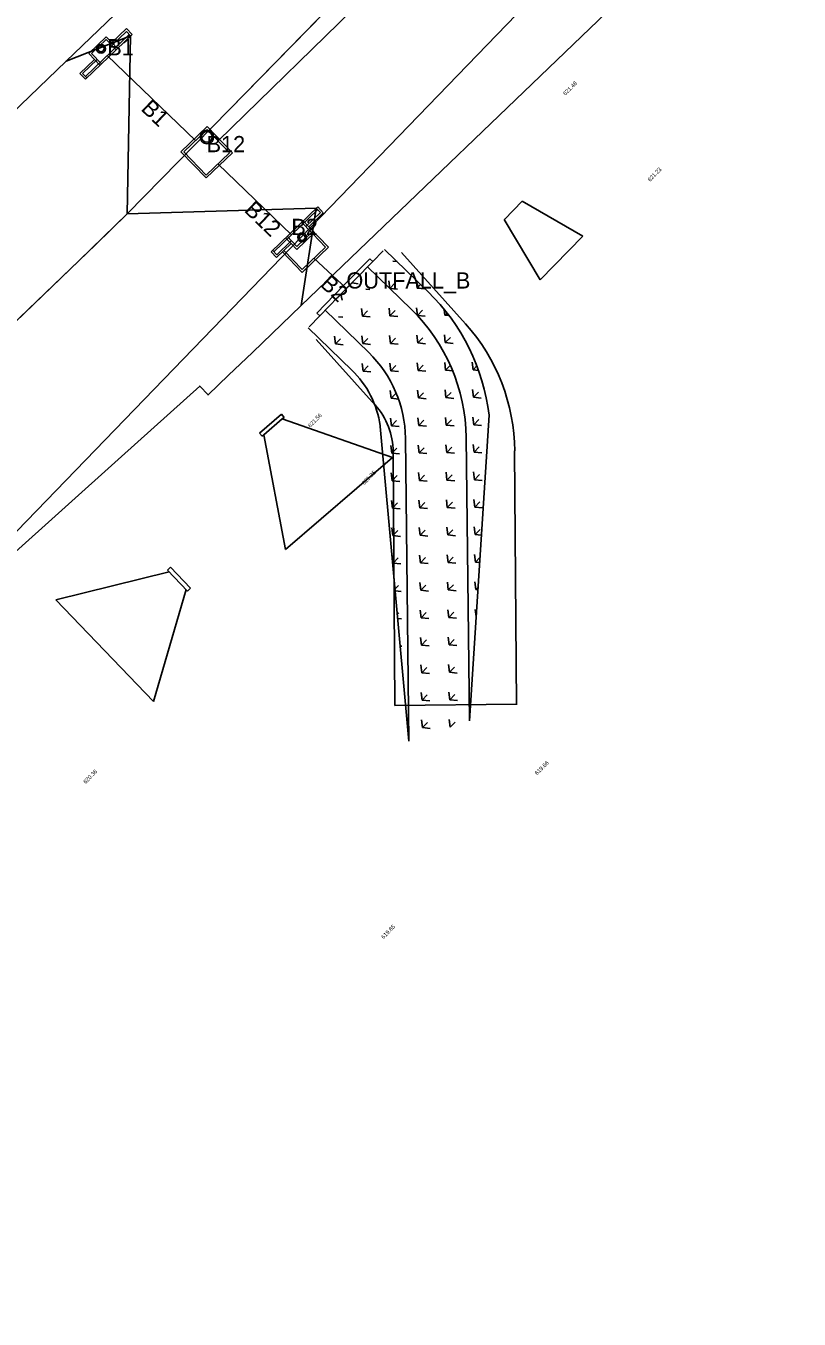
# Model space of a CAD drawing. Extents: x 2253035 to 2279930, y 13774972 to 13793443.
# Drawn here: x 2255239.2 to 2255430.2, y 13790865.4 to 13791184.9 of the extents above; entities that cross this region are included whole.
import ezdxf

# ---------------------------------------------------------------- set-up
doc = ezdxf.new("R2010")
doc.units = 0
for name, color, linetype in [('E_Utility_ATT_Fiber', 7, 'Continuous'), ('E_Utility_ATT_Xbox', 7, 'Continuous'), ('E_Utility_Electric_Overhead Electric Power Line_OE_Description', 7, 'Continuous'), ('E_Utility_Electric_Overhead Electric Power Line_OE_Elevation', 7, 'Continuous'), ('E_Utility_Electric_Service Pole Electric_SPLE_point', 7, 'Continuous'), ('E_Utility_Fiber Optic_Fiber Optic Cable_FOC', 7, 'Continuous'), ('E_Utility_Gas_Gas Line_GL_Description', 7, 'Continuous'), ('E_Utility_Gas_Gas Line_GL_Elevation', 7, 'Continuous'), ('E_Utility_Telephone_Manhole Telephone_MHT_Description', 7, 'Continuous'), ('E_Utility_Water_Water Line_WL_Elevation', 7, 'Continuous'), ('E_Utility_Water_Water Valve_WV_Elevation', 7, 'Continuous')]:
    doc.layers.add(name, color=color, linetype=linetype)

msp = doc.modelspace()

# ---------------------------------------------------------------- linework, layer by layer
at = {"layer": 'E_Utility_ATT_Fiber'}
for p, q in [((2255331.7, 13791207.4), (2255289.47, 13791164.26)), ((2255307.2, 13791115.81), (2255399.18, 13791204.14)), ((2255265.06, 13791182.43), (2255249.13, 13791176.15)), ((2255249.13, 13791176.15), (2255265.06, 13791182.43)), ((2255264.21, 13791138.47), (2255265.06, 13791182.43)), ((2255265.06, 13791182.43), (2255264.21, 13791138.47)), ((2255264.21, 13791138.47), (2255289.47, 13791164.26)), ((2255289.47, 13791164.26), (2255264.21, 13791138.47)), ((2255256.38, 13791130.82), (2255264.21, 13791138.47)), ((2255264.21, 13791138.47), (2255310.9, 13791139.84)), ((2255310.9, 13791139.84), (2255307.2, 13791115.81)), ((2255252.37, 13791126.93), (2255256.38, 13791130.82)), ((2255062.92, 13790944.99), (2255252.37, 13791126.93))]:
    msp.add_line(p, q, dxfattribs=at)
for points in [[(2255375.55, 13791298.97), (2255354.02, 13791277.09), (2255341.17, 13791264.54), (2255249.13, 13791176.15)], [(2255289.47, 13791164.26), (2255369.58, 13791246.26), (2255386.15, 13791263.21)], [(2255249.13, 13791176.15), (2255226.58, 13791154.5), (2255225.88, 13791155.18)]]:
    msp.add_lwpolyline(points, dxfattribs=at)
msp.add_lwpolyline([(2255310.9, 13791139.84), (2255307.22, 13791115.83), (2255295.13, 13791104.21), (2255289.23, 13791098.55), (2255284.2, 13791093.71), (2255282.12, 13791095.87), (2255262.79, 13791078.49), (2255121.12, 13790951.06), (2255099.87, 13790931.94), (2255092.37, 13790924.75), (2255033.91, 13790865.37), (2255030.7, 13790879.5), (2255003.84, 13790885.26), (2255037.34, 13790919.6), (2255062.92, 13790944.99), (2255252.37, 13791126.93), (2255264.21, 13791138.47)], close=True, dxfattribs=at)
at = {"layer": 'E_Utility_ATT_Xbox'}
for p, q in [((2255257.22, 13791179.76), (2255257.22, 13791179.76)), ((2255258.26, 13791178.68), (2255258.26, 13791178.68)), ((2255260.06, 13791180.41), (2255260.06, 13791180.41)), ((2255256.46, 13791176.95), (2255256.46, 13791176.95)), ((2255259.3, 13791177.6), (2255259.3, 13791177.6)), ((2255281.06, 13791156.55), (2255281.06, 13791156.55)), ((2255286.71, 13791156.44), (2255286.71, 13791156.44)), ((2255283.83, 13791153.67), (2255283.83, 13791153.67)), ((2255280.94, 13791150.9), (2255280.94, 13791150.9)), ((2255286.6, 13791150.78), (2255286.6, 13791150.78)), ((2255304.77, 13791133.23), (2255304.77, 13791133.23)), ((2255310.43, 13791133.11), (2255310.43, 13791133.11)), ((2255304.66, 13791127.57), (2255304.66, 13791127.57)), ((2255307.54, 13791130.34), (2255307.54, 13791130.34)), ((2255310.31, 13791127.46), (2255310.31, 13791127.46)), ((2255316.98, 13791118.56), (2255319.77, 13791121.43)), ((2255319.77, 13791121.43), (2255321.23, 13791121.14)), ((2255316.98, 13791118.56), (2255317.3, 13791117.11)), ((2255318.37, 13791119.99), (2255318.37, 13791119.99)), ((2255318.37, 13791119.99), (2255318.37, 13791119.99))]:
    msp.add_line(p, q, dxfattribs=at)
at = {"layer": 'E_Utility_Electric_Overhead Electric Power Line_OE_Description'}
for p, q in [((2255327.45, 13791129.32), (2255324.85, 13791126.65)), ((2255327.79, 13791129.66), (2255338.55, 13791119.19)), ((2255323.61, 13791125.37), (2255334.36, 13791114.89)), ((2255329.84, 13791126.73), (2255330.88, 13791126.63)), ((2255329.05, 13791120.03), (2255328.82, 13791121.93)), ((2255330.31, 13791121.32), (2255329.05, 13791120.03)), ((2255335.84, 13791120.11), (2255335.6, 13791122.02)), ((2255323.13, 13791119.86), (2255324.18, 13791119.76)), ((2255329.05, 13791120.03), (2255330.96, 13791119.84)), ((2255336.7, 13791120.99), (2255335.84, 13791120.11)), ((2255335.84, 13791120.11), (2255337.75, 13791119.92)), ((2255322.35, 13791113.16), (2255322.11, 13791115.06)), ((2255329.13, 13791113.24), (2255328.9, 13791115.15)), ((2255335.92, 13791113.32), (2255335.69, 13791115.23)), ((2255342.71, 13791113.41), (2255342.54, 13791114.81)), ((2255309.15, 13791110.53), (2255311.77, 13791113.22)), ((2255313.14, 13791114.62), (2255323.88, 13791104.15)), ((2255316.43, 13791112.99), (2255317.47, 13791112.88)), ((2255323.6, 13791114.44), (2255322.35, 13791113.16)), ((2255322.35, 13791113.16), (2255324.26, 13791112.97)), ((2255330.39, 13791114.53), (2255329.13, 13791113.24)), ((2255329.13, 13791113.24), (2255331.05, 13791113.05)), ((2255337.18, 13791114.61), (2255335.92, 13791113.32)), ((2255335.92, 13791113.32), (2255337.83, 13791113.13)), ((2255343.23, 13791113.94), (2255342.71, 13791113.41)), ((2255342.71, 13791113.41), (2255343.71, 13791113.31)), ((2255308.95, 13791110.32), (2255319.7, 13791099.86)), ((2255329.22, 13791106.45), (2255328.98, 13791108.36)), ((2255336.01, 13791106.54), (2255335.77, 13791108.44)), ((2255342.79, 13791106.62), (2255342.56, 13791108.52)), ((2255315.64, 13791106.29), (2255315.41, 13791108.19)), ((2255316.9, 13791107.57), (2255315.64, 13791106.29)), ((2255315.64, 13791106.29), (2255317.55, 13791106.1)), ((2255322.43, 13791106.37), (2255322.19, 13791108.27)), ((2255323.69, 13791107.66), (2255322.43, 13791106.37)), ((2255322.43, 13791106.37), (2255324.34, 13791106.18)), ((2255330.47, 13791107.74), (2255329.22, 13791106.45)), ((2255329.22, 13791106.45), (2255331.13, 13791106.26)), ((2255337.26, 13791107.82), (2255336.01, 13791106.54)), ((2255336.01, 13791106.54), (2255337.92, 13791106.35)), ((2255344.05, 13791107.91), (2255342.79, 13791106.62)), ((2255342.79, 13791106.62), (2255344.7, 13791106.43)), ((2255322.51, 13791099.58), (2255322.28, 13791101.49)), ((2255323.77, 13791100.87), (2255322.51, 13791099.58)), ((2255322.51, 13791099.58), (2255324.43, 13791099.39)), ((2255329.3, 13791099.66), (2255329.07, 13791101.57)), ((2255330.56, 13791100.95), (2255329.3, 13791099.66)), ((2255329.3, 13791099.66), (2255331.21, 13791099.48)), ((2255336.09, 13791099.75), (2255335.85, 13791101.65)), ((2255337.35, 13791101.04), (2255336.09, 13791099.75)), ((2255336.09, 13791099.75), (2255338, 13791099.56)), ((2255342.88, 13791099.83), (2255342.64, 13791101.74)), ((2255344.13, 13791101.12), (2255342.88, 13791099.83)), ((2255342.88, 13791099.83), (2255344.79, 13791099.64)), ((2255349.66, 13791099.91), (2255349.43, 13791101.82)), ((2255350.59, 13791100.86), (2255349.66, 13791099.91)), ((2255349.66, 13791099.91), (2255350.98, 13791099.78)), ((2255329.38, 13791092.88), (2255329.15, 13791094.78)), ((2255330.64, 13791094.16), (2255329.38, 13791092.88)), ((2255329.38, 13791092.88), (2255331.3, 13791092.69)), ((2255336.17, 13791092.96), (2255335.94, 13791094.87)), ((2255337.43, 13791094.25), (2255336.17, 13791092.96)), ((2255336.17, 13791092.96), (2255338.08, 13791092.77)), ((2255342.96, 13791093.04), (2255342.72, 13791094.95)), ((2255344.22, 13791094.33), (2255342.96, 13791093.04)), ((2255342.96, 13791093.04), (2255344.87, 13791092.85)), ((2255349.75, 13791093.13), (2255349.51, 13791095.03)), ((2255351, 13791094.41), (2255349.75, 13791093.13)), ((2255349.75, 13791093.13), (2255351.66, 13791092.94)), ((2255333.81, 13791008.15), (2255326.65, 13791086.82)), ((2255329.47, 13791086.09), (2255329.23, 13791088)), ((2255330.72, 13791087.38), (2255329.47, 13791086.09)), ((2255329.47, 13791086.09), (2255331.38, 13791085.9)), ((2255336.26, 13791086.17), (2255336.02, 13791088.08)), ((2255337.51, 13791087.46), (2255336.26, 13791086.17)), ((2255336.26, 13791086.17), (2255338.17, 13791085.98)), ((2255343.04, 13791086.26), (2255342.81, 13791088.16)), ((2255344.3, 13791087.54), (2255343.04, 13791086.26)), ((2255343.04, 13791086.26), (2255344.95, 13791086.07)), ((2255353.59, 13791088.7), (2255348.74, 13791013.22)), ((2255349.83, 13791086.34), (2255349.6, 13791088.24)), ((2255351.09, 13791087.63), (2255349.83, 13791086.34)), ((2255349.83, 13791086.34), (2255351.74, 13791086.15)), ((2255332.95, 13791083), (2255333.8, 13791008.15)), ((2255347.95, 13791083.17), (2255348.74, 13791013.22)), ((2255329.55, 13791079.3), (2255329.32, 13791081.21)), ((2255330.81, 13791080.59), (2255329.55, 13791079.3)), ((2255336.34, 13791079.38), (2255336.1, 13791081.29)), ((2255337.6, 13791080.67), (2255336.34, 13791079.38)), ((2255343.13, 13791079.47), (2255342.89, 13791081.37)), ((2255344.38, 13791080.76), (2255343.13, 13791079.47)), ((2255349.91, 13791079.55), (2255349.68, 13791081.46)), ((2255351.17, 13791080.84), (2255349.91, 13791079.55)), ((2255329.55, 13791079.3), (2255331.46, 13791079.11)), ((2255336.34, 13791079.38), (2255338.25, 13791079.2)), ((2255343.13, 13791079.47), (2255345.04, 13791079.28)), ((2255349.91, 13791079.55), (2255351.83, 13791079.36)), ((2255329.63, 13791072.51), (2255329.4, 13791074.42)), ((2255330.89, 13791073.8), (2255329.63, 13791072.51)), ((2255336.42, 13791072.6), (2255336.19, 13791074.5)), ((2255337.68, 13791073.88), (2255336.42, 13791072.6)), ((2255343.21, 13791072.68), (2255342.97, 13791074.59)), ((2255344.47, 13791073.97), (2255343.21, 13791072.68)), ((2255350, 13791072.76), (2255349.76, 13791074.67)), ((2255351.25, 13791074.05), (2255350, 13791072.76)), ((2255329.63, 13791072.51), (2255331.55, 13791072.32)), ((2255336.42, 13791072.6), (2255338.33, 13791072.41)), ((2255343.21, 13791072.68), (2255345.12, 13791072.49)), ((2255350, 13791072.76), (2255351.91, 13791072.57)), ((2255329.72, 13791065.73), (2255329.48, 13791067.63)), ((2255330.97, 13791067.01), (2255329.72, 13791065.73)), ((2255336.51, 13791065.81), (2255336.27, 13791067.72)), ((2255337.76, 13791067.1), (2255336.51, 13791065.81)), ((2255343.29, 13791065.89), (2255343.06, 13791067.8)), ((2255344.55, 13791067.18), (2255343.29, 13791065.89)), ((2255350.08, 13791065.98), (2255349.85, 13791067.88)), ((2255351.34, 13791067.26), (2255350.08, 13791065.98)), ((2255329.72, 13791065.73), (2255331.63, 13791065.54)), ((2255336.51, 13791065.81), (2255338.42, 13791065.62)), ((2255343.29, 13791065.89), (2255345.2, 13791065.7)), ((2255350.08, 13791065.98), (2255351.99, 13791065.79)), ((2255329.8, 13791058.94), (2255329.57, 13791060.84)), ((2255336.59, 13791059.02), (2255336.35, 13791060.93)), ((2255343.38, 13791059.1), (2255343.14, 13791061.01)), ((2255344.63, 13791060.39), (2255343.38, 13791059.1)), ((2255350.16, 13791059.19), (2255349.93, 13791061.09)), ((2255351.42, 13791060.48), (2255350.16, 13791059.19)), ((2255331.06, 13791060.23), (2255329.8, 13791058.94)), ((2255329.8, 13791058.94), (2255331.71, 13791058.75)), ((2255337.85, 13791060.31), (2255336.59, 13791059.02)), ((2255336.59, 13791059.02), (2255338.5, 13791058.83)), ((2255343.38, 13791059.1), (2255345.29, 13791058.92)), ((2255350.16, 13791059.19), (2255351.69, 13791059.04)), ((2255329.88, 13791052.15), (2255329.65, 13791054.06)), ((2255336.67, 13791052.23), (2255336.44, 13791054.14)), ((2255343.46, 13791052.32), (2255343.22, 13791054.22)), ((2255350.25, 13791052.4), (2255350.01, 13791054.31)), ((2255331.14, 13791053.44), (2255329.88, 13791052.15)), ((2255329.88, 13791052.15), (2255331.8, 13791051.96)), ((2255337.93, 13791053.52), (2255336.67, 13791052.23)), ((2255336.67, 13791052.23), (2255338.58, 13791052.04)), ((2255344.72, 13791053.6), (2255343.46, 13791052.32)), ((2255343.46, 13791052.32), (2255345.37, 13791052.13)), ((2255351.33, 13791053.51), (2255350.25, 13791052.4)), ((2255350.25, 13791052.4), (2255351.25, 13791052.3)), ((2255331.22, 13791046.65), (2255330.39, 13791045.79)), ((2255330.43, 13791045.32), (2255331.88, 13791045.17)), ((2255336.76, 13791045.45), (2255336.52, 13791047.35)), ((2255338.01, 13791046.73), (2255336.76, 13791045.45)), ((2255336.76, 13791045.45), (2255338.67, 13791045.26)), ((2255343.54, 13791045.53), (2255343.31, 13791047.44)), ((2255344.8, 13791046.82), (2255343.54, 13791045.53)), ((2255343.54, 13791045.53), (2255345.45, 13791045.34)), ((2255350.33, 13791045.61), (2255350.1, 13791047.52)), ((2255350.86, 13791046.15), (2255350.33, 13791045.61)), ((2255350.33, 13791045.61), (2255350.82, 13791045.56)), ((2255331.31, 13791039.86), (2255330.96, 13791039.5)), ((2255331.05, 13791038.48), (2255331.96, 13791038.39)), ((2255336.84, 13791038.66), (2255336.6, 13791040.56)), ((2255338.1, 13791039.95), (2255336.84, 13791038.66)), ((2255336.84, 13791038.66), (2255338.75, 13791038.47)), ((2255343.63, 13791038.74), (2255343.39, 13791040.65)), ((2255344.88, 13791040.03), (2255343.63, 13791038.74)), ((2255343.63, 13791038.74), (2255345.54, 13791038.55)), ((2255350.4, 13791038.97), (2255350.18, 13791040.73)), ((2255331.67, 13791031.63), (2255332.05, 13791031.6)), ((2255336.92, 13791031.87), (2255336.69, 13791033.78)), ((2255338.18, 13791033.16), (2255336.92, 13791031.87)), ((2255336.92, 13791031.87), (2255338.83, 13791031.68)), ((2255343.71, 13791031.95), (2255343.47, 13791033.86)), ((2255344.97, 13791033.24), (2255343.71, 13791031.95)), ((2255343.71, 13791031.95), (2255345.62, 13791031.76)), ((2255337.01, 13791025.08), (2255336.77, 13791026.99)), ((2255338.26, 13791026.37), (2255337.01, 13791025.08)), ((2255343.79, 13791025.17), (2255343.56, 13791027.07)), ((2255345.05, 13791026.45), (2255343.79, 13791025.17)), ((2255337.01, 13791025.08), (2255338.92, 13791024.89)), ((2255343.79, 13791025.17), (2255345.7, 13791024.98)), ((2255337.09, 13791018.29), (2255336.85, 13791020.2)), ((2255338.35, 13791019.58), (2255337.09, 13791018.29)), ((2255343.88, 13791018.38), (2255343.64, 13791020.28)), ((2255345.13, 13791019.67), (2255343.88, 13791018.38)), ((2255337.09, 13791018.29), (2255339, 13791018.11)), ((2255343.88, 13791018.38), (2255345.79, 13791018.19)), ((2255337.17, 13791011.51), (2255336.94, 13791013.41)), ((2255338.43, 13791012.8), (2255337.17, 13791011.51)), ((2255343.96, 13791011.6), (2255343.72, 13791013.5)), ((2255345.22, 13791012.88), (2255343.97, 13791011.6)), ((2255337.17, 13791011.51), (2255339.08, 13791011.32))]:
    msp.add_line(p, q, dxfattribs=at)
for radius, start in [(51, 6.7965), (45, 0.6476), (30, 0.6476), (24, 8.1355)]:
    msp.add_arc((2255302.95, 13791082.67), radius, start, 45.7508, dxfattribs=at)
at = {"layer": 'E_Utility_Electric_Service Pole Electric_SPLE_point'}
for p, q in [((2255331.94, 13791128.89), (2255347.8, 13791111.25)), ((2255310.92, 13791107.4), (2255325.48, 13791091.2)), ((2255329.92, 13791079.66), (2255330.36, 13791016.95)), ((2255359.92, 13791079.87), (2255360.36, 13791017.16)), ((2255360.36, 13791017.29), (2255330.36, 13791016.95))]:
    msp.add_line(p, q, dxfattribs=at)
for radius in [47.5, 17.5]:
    msp.add_arc((2255312.43, 13791079.54), radius, 0.3995, 41.8571, dxfattribs=at)
at = {"layer": 'E_Utility_Fiber Optic_Fiber Optic Cable_FOC'}
for p, q in [((2255253.88, 13791171.7), (2255265.42, 13791182.78)), ((2255253.89, 13791172.4), (2255264.71, 13791182.79)), ((2255254.71, 13791178.05), (2255259.04, 13791182.2)), ((2255259.04, 13791182.2), (2255260.42, 13791180.76)), ((2255260.41, 13791180.05), (2255264.02, 13791183.52)), ((2255260.42, 13791180.76), (2255264.03, 13791184.22)), ((2255264.02, 13791183.52), (2255265.06, 13791182.43)), ((2255264.03, 13791184.22), (2255265.42, 13791182.78)), ((2255255.42, 13791178.03), (2255259.03, 13791181.49)), ((2255259.03, 13791181.49), (2255261.45, 13791178.97)), ((2255260.42, 13791180.76), (2255261.81, 13791179.32)), ((2255252.49, 13791173.14), (2255256.1, 13791176.6)), ((2255253.2, 13791173.13), (2255256.8, 13791176.59)), ((2255254.71, 13791178.05), (2255256.1, 13791176.6)), ((2255255.42, 13791178.03), (2255257.84, 13791175.51)), ((2255256.1, 13791176.6), (2255257.48, 13791175.16)), ((2255252.49, 13791173.14), (2255253.88, 13791171.7)), ((2255253.2, 13791173.13), (2255254.24, 13791172.04)), ((2255277.46, 13791153.8), (2255283.96, 13791160.03)), ((2255283.96, 13791160.03), (2255290.19, 13791153.54)), ((2255278.17, 13791153.78), (2255283.94, 13791159.32)), ((2255283.94, 13791159.32), (2255289.48, 13791153.55)), ((2255283.7, 13791147.3), (2255277.46, 13791153.8)), ((2255283.71, 13791148.01), (2255278.17, 13791153.78)), ((2255290.19, 13791153.54), (2255283.7, 13791147.3)), ((2255289.48, 13791153.55), (2255283.71, 13791148.01)), ((2255311.28, 13791140.17), (2255299.74, 13791129.09)), ((2255311.26, 13791139.46), (2255300.44, 13791129.07)), ((2255311.96, 13791138.74), (2255308.35, 13791135.28)), ((2255312.66, 13791138.73), (2255309.06, 13791135.26)), ((2255311.96, 13791138.74), (2255310.92, 13791139.82)), ((2255312.66, 13791138.73), (2255311.28, 13791140.17)), ((2255309.74, 13791133.84), (2255307.31, 13791136.36)), ((2255309.06, 13791135.26), (2255307.67, 13791136.71)), ((2255310.44, 13791133.82), (2255309.06, 13791135.26)), ((2255313.91, 13791130.21), (2255309.06, 13791135.26)), ((2255304.73, 13791131.11), (2255301.12, 13791127.64)), ((2255304.74, 13791131.81), (2255301.14, 13791128.35)), ((2255304.73, 13791131.11), (2255303.34, 13791132.55)), ((2255306.13, 13791130.37), (2255303.7, 13791132.9)), ((2255306.11, 13791129.66), (2255304.73, 13791131.11)), ((2255310.44, 13791133.82), (2255306.11, 13791129.66)), ((2255309.74, 13791133.84), (2255306.13, 13791130.37)), ((2255313.2, 13791130.23), (2255310.08, 13791133.47)), ((2255301.12, 13791127.64), (2255299.74, 13791129.09)), ((2255301.14, 13791128.35), (2255300.1, 13791129.43)), ((2255302.57, 13791129.03), (2255307.41, 13791123.98)), ((2255302.93, 13791129.38), (2255307.43, 13791124.69)), ((2255307.41, 13791123.98), (2255313.91, 13791130.21)), ((2255307.43, 13791124.69), (2255313.2, 13791130.23))]:
    msp.add_line(p, q, dxfattribs=at)
for centre, radius in [((2255257.74, 13791179.22), 1.08), ((2255257.74, 13791179.22), 0.75), ((2255283.9, 13791157.44), 1.67), ((2255283.9, 13791157.44), 1.33), ((2255307.41, 13791132.64), 1.08), ((2255307.41, 13791132.64), 0.75)]:
    msp.add_circle(centre, radius, dxfattribs=at)
at = {"layer": 'E_Utility_Gas_Gas Line_GL_Description'}
for p, q in [((2255402.34, 13791269.51), (2255286.71, 13791156.44)), ((2255259.3, 13791177.6), (2255281.06, 13791156.55)), ((2255286.6, 13791150.78), (2255304.77, 13791133.23)), ((2255310.31, 13791127.46), (2255318.37, 13791119.99))]:
    msp.add_line(p, q, dxfattribs=at)
at = {"layer": 'E_Utility_Telephone_Manhole Telephone_MHT_Description'}
for p, q in [((2255324.85, 13791126.66), (2255324.13, 13791127.36)), ((2255315.85, 13791117.41), (2255320.86, 13791122.54)), ((2255316.22, 13791117.79), (2255320.53, 13791122.2)), ((2255316.24, 13791117.85), (2255316.96, 13791118.59)), ((2255316.96, 13791118.59), (2255318.35, 13791120.02)), ((2255311.76, 13791113.23), (2255316.24, 13791117.85)), ((2255316.1, 13791117.67), (2255316.22, 13791117.79)), ((2255311.05, 13791113.93), (2255311.76, 13791113.23))]:
    msp.add_line(p, q, dxfattribs=at)
for points in [[(2255324.13, 13791127.36), (2255317.62, 13791120.7), (2255311.05, 13791113.93)], [(2255318.35, 13791120.02), (2255319.75, 13791121.45), (2255320.43, 13791122.15), (2255324.85, 13791126.66)]]:
    msp.add_lwpolyline(points, dxfattribs=at)
at = {"layer": 'E_Utility_Water_Water Line_WL_Elevation'}
for p, q in [((2255361.79, 13791141.54), (2255357.44, 13791137.08)), ((2255376.8, 13791132.93), (2255361.79, 13791141.54)), ((2255357.44, 13791137.08), (2255357.37, 13791137.01)), ((2255357.37, 13791137.01), (2255366.26, 13791122.13)), ((2255366.26, 13791122.13), (2255376.8, 13791132.93)), ((2255302.3, 13791088.91), (2255296.86, 13791084.24)), ((2255302.51, 13791087.77), (2255297.96, 13791083.86)), ((2255302.95, 13791088.15), (2255302.3, 13791088.91)), ((2255329.75, 13791078.23), (2255302.51, 13791087.77)), ((2255296.86, 13791084.24), (2255297.52, 13791083.48)), ((2255297.96, 13791083.86), (2255303.32, 13791055.5)), ((2255303.32, 13791055.5), (2255329.75, 13791078.23)), ((2255274.9, 13791051.12), (2255274.18, 13791050.42)), ((2255274.9, 13791051.12), (2255279.86, 13791045.95)), ((2255274.58, 13791050), (2255246.55, 13791043.1)), ((2255274.18, 13791050.42), (2255279.14, 13791045.25)), ((2255278.74, 13791045.67), (2255270.7, 13791017.95)), ((2255279.86, 13791045.95), (2255279.14, 13791045.25)), ((2255246.55, 13791043.1), (2255270.7, 13791017.95))]:
    msp.add_line(p, q, dxfattribs=at)
msp.add_lwpolyline([(2255297.52, 13791083.48), (2255297.96, 13791083.86), (2255302.51, 13791087.77), (2255302.95, 13791088.15)], dxfattribs=at)
at = {"layer": 'E_Utility_Water_Water Valve_WV_Elevation'}
msp.add_lwpolyline([(2255623, 13791457.45), (2255517, 13791344.43), (2255472.8, 13791295.19), (2255379.75, 13791207.78), (2255198.17, 13791020.02), (2255136.03, 13790956.76), (2255067.98, 13791022.64), (2255178.24, 13791137.81), (2255292.07, 13791256.47), (2255389.41, 13791303.46), (2255390.98, 13791330.06), (2255459.85, 13791397.22)], dxfattribs=at)

# ---------------------------------------------------------------- texts
at = {"layer": 'E_Utility_Electric_Overhead Electric Power Line_OE_Elevation'}
for s, p in [('621.48', (2255372.48, 13791167.59)), ('621.23', (2255393.36, 13791146.31)), ('621.56', (2255309.44, 13791085.55)), ('621.35', (2255322.78, 13791071.41)), ('619.66', (2255365.5, 13790999.7)), ('620.36', (2255253.96, 13790997.56)), ('619.65', (2255327.55, 13790959.22))]:
    msp.add_text(s, height=1, rotation=45.7508, dxfattribs=at).set_placement(p)
at = {"layer": 'E_Utility_Gas_Gas Line_GL_Elevation'}
for s, p in [('B1', (2255259.3, 13791177.6)), ('B12', (2255283.83, 13791153.67)), ('B2', (2255304.77, 13791133.23)), ('OUTFALL_B', (2255318.37, 13791119.99))]:
    msp.add_text(s, height=4, dxfattribs=at).set_placement(p)
for s, rotation, p in [('B1', 315.948, (2255267.4, 13791164.2)), ('B12', 315.9967, (2255292.91, 13791139.13)), ('B2', 317.1985, (2255311.63, 13791120.79))]:
    msp.add_text(s, height=4, rotation=rotation, dxfattribs=at).set_placement(p)

doc.saveas('drawing.dxf')
